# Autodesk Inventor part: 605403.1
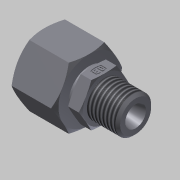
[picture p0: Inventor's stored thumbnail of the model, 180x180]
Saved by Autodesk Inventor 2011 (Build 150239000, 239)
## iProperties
Created: 2015-12
Part Number: 605403.1
Material: Сталь
Document SubType Name: Modeling
Designer: Дорохин
Mass: 79.5731 g
Surface Area: 49.2785 cm^2
Volume: 10.1367 cm^3
Density: 7.85 g/cm^3
Стандарт преобразования: STEP AP203
Имя файла: C:/Users/dorohin/Documents/EO Tube end reducer RED12_06SOMDCF.stp
Постпроцессор: Build: 309, Release: 2011 SP2 - Date: Thu 04/28/2011
Отправленные единицы: миллиметр
Неопределенность: 1.0000000000000002e-06
Author: Дорохин
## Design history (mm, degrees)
feature "БазТело1"
feature "Резьба1" dims "d0" = 10, "d1" = 0
feature "Резьба2" dims "d2" = 10, "d3" = 0
node "1"
